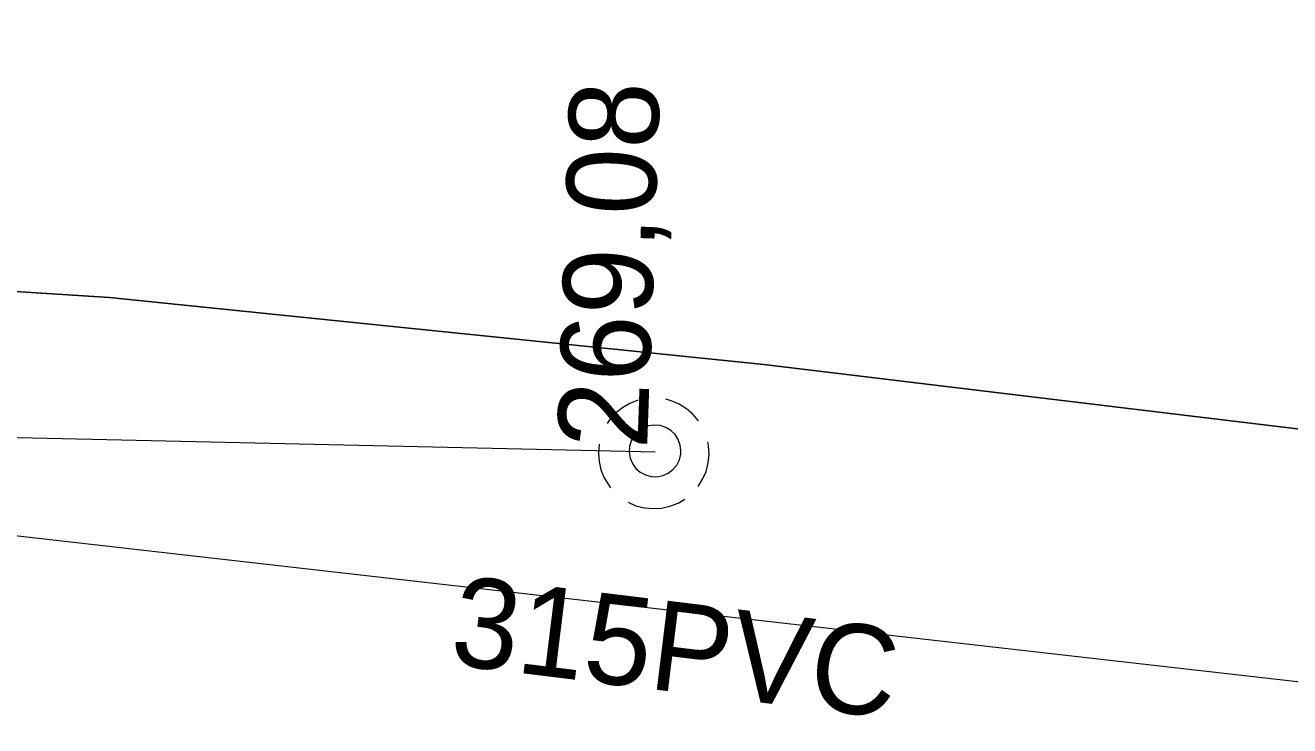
# Model space of a CAD drawing. Extents: x -732096 to -731933, y -1048703 to -1047964.
# Drawn here: x -731974.77 to -731963.51, y -1048640.38 to -1048634.13 of the extents above; entities that cross this region are included whole.
import ezdxf

# ---------------------------------------------------------------- set-up
doc = ezdxf.new("R2010")
doc.units = 0
doc.header["$LTSCALE"] = 0.32
doc.layers.add('1', color=7, linetype='Continuous')
for name, color, linetype, lineweight in [('18', 7, 'Continuous', 13), ('20', 7, 'Continuous', 13), ('8', 7, 'Continuous', 13)]:
    doc.layers.add(name, color=color, linetype=linetype, lineweight=lineweight)

msp = doc.modelspace()

# ---------------------------------------------------------------- linework, layer by layer
at = {"layer": '18'}
for points in [[(-731969.313, -1048637.477), (-731969.384, -1048637.505), (-731969.451, -1048637.544), (-731969.511, -1048637.592), (-731969.562, -1048637.649), (-731969.586, -1048637.683)], [(-731968.772, -1048637.66), (-731968.822, -1048637.602), (-731968.88, -1048637.552), (-731968.945, -1048637.511), (-731969.016, -1048637.482), (-731969.065, -1048637.468)], [(-731969.658, -1048637.869), (-731969.664, -1048637.946), (-731969.659, -1048638.023), (-731969.642, -1048638.098), (-731969.613, -1048638.169), (-731969.573, -1048638.235), (-731969.557, -1048638.257)], [(-731968.777, -1048638.246), (-731968.736, -1048638.181), (-731968.705, -1048638.111), (-731968.686, -1048638.036), (-731968.678, -1048637.96), (-731968.683, -1048637.883), (-731968.689, -1048637.848)], [(-731969.4, -1048638.386), (-731969.33, -1048638.417), (-731969.255, -1048638.436), (-731969.179, -1048638.443), (-731969.102, -1048638.438), (-731969.027, -1048638.421), (-731968.955, -1048638.393), (-731968.895, -1048638.358)]]:
    msp.add_lwpolyline(points, dxfattribs=at)
msp.add_lwpolyline([(-731968.929, -1048637.929), (-731968.935, -1048637.877), (-731968.953, -1048637.827), (-731968.981, -1048637.783), (-731969.019, -1048637.746), (-731969.064, -1048637.719), (-731969.114, -1048637.703), (-731969.166, -1048637.698), (-731969.218, -1048637.705), (-731969.267, -1048637.724), (-731969.311, -1048637.754), (-731969.346, -1048637.793), (-731969.372, -1048637.838), (-731969.387, -1048637.889), (-731969.39, -1048637.941), (-731969.382, -1048637.993), (-731969.361, -1048638.041), (-731969.331, -1048638.084), (-731969.291, -1048638.119), (-731969.245, -1048638.143), (-731969.194, -1048638.157), (-731969.142, -1048638.159), (-731969.09, -1048638.149), (-731969.042, -1048638.127), (-731969, -1048638.095), (-731968.967, -1048638.055), (-731968.943, -1048638.008), (-731968.931, -1048637.957)], close=True, dxfattribs=at)
at = {"layer": '20'}
msp.add_line((-731959.989, -1048640.379), (-731976.76, -1048638.47), dxfattribs=at)
msp.add_line((-731959.989, -1048640.379), (-731976.76, -1048638.47), dxfattribs=at)
msp.add_lwpolyline([(-731969.16, -1048637.94), (-731982.899, -1048637.629), (-731984.98, -1048611.47)], dxfattribs=at)
msp.add_lwpolyline([(-731969.16, -1048637.94), (-731982.899, -1048637.629), (-731984.98, -1048611.47)], dxfattribs=at)
at = {"layer": '8', "lineweight": 25}
msp.add_lwpolyline([(-731978.579, -1048636.27), (-731974.02, -1048636.56), (-731968.19, -1048637.159), (-731956.25, -1048638.6), (-731946.058, -1048639.529)], dxfattribs=at)

# ---------------------------------------------------------------- texts
at = {"layer": '1'}
for s, rotation, p in [('269,08', 88, (-731969.231, -1048637.918)), ('315PVC', 353, (-731971.003, -1048639.83))]:
    msp.add_text(s, height=0.8, rotation=rotation, dxfattribs=at).set_placement(p)

doc.saveas('drawing.dxf')
